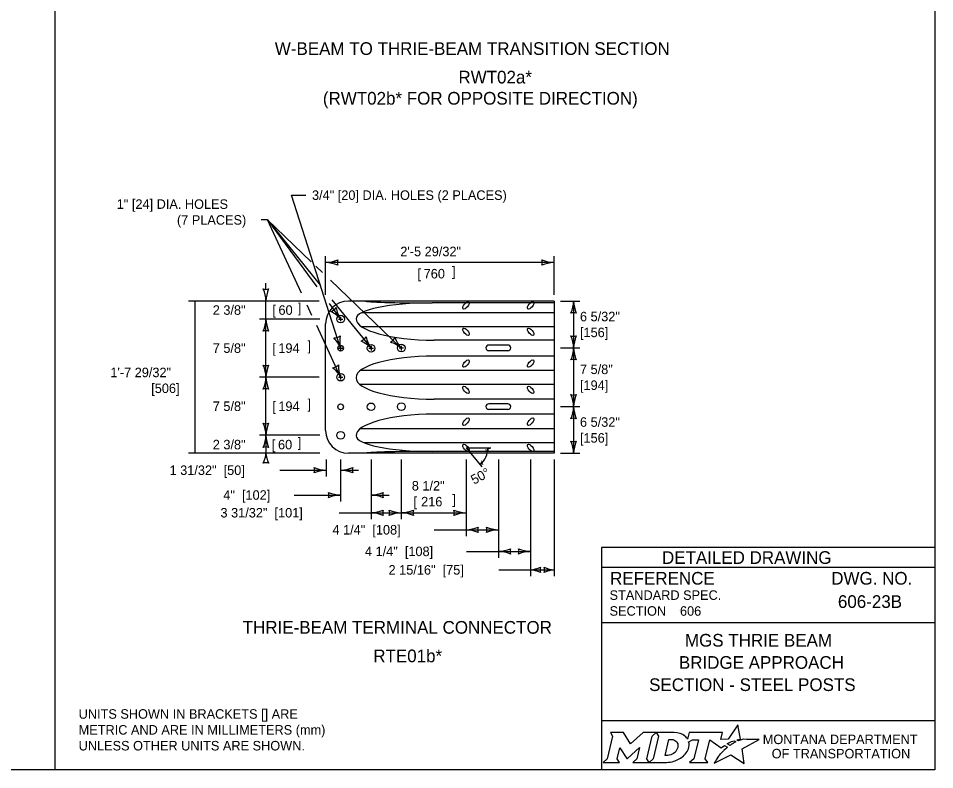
# Model space of a CAD drawing. Extents: x 49991 to 50160, y 49948 to 50051.
# Drawn here: x 50010.97 to 50016.75, y 49987.8 to 49992.54 of the extents above; entities that cross this region are included whole.
import ezdxf

# ---------------------------------------------------------------- set-up
doc = ezdxf.new("R2010")
doc.units = 0
for name, color, linetype in [('Default', 7, 'Continuous'), ('Level 1', 7, 'Continuous'), ('Level 10', 7, 'Continuous'), ('Level 2', 7, 'Continuous'), ('Level 3', 7, 'Continuous'), ('Level 5', 7, 'Continuous')]:
    doc.layers.add(name, color=color, linetype=linetype)

# ---------------------------------------------------------------- blocks, each defined once
blk = doc.blocks.new('ARRP')
at = {"layer": 'Level 10'}
for centre, major_axis, start_param, end_param in [((0.018, 0.564), (0, -0.565), 5.889718, 6.241987), ((-0.253, 0), (0, -0.139), 1.25906, 1.882533), ((0.023, -0.591), (0, 0.592), 0.049346, 0.385319)]:
    blk.add_ellipse(centre, major_axis=major_axis, ratio=0.77736, start_param=start_param, end_param=end_param, dxfattribs=at)

msp = doc.modelspace()

# ---------------------------------------------------------------- linework, layer by layer
at = {"layer": 'Default'}
for points in [[(50015.5126, 49987.9811), (50015.5023, 49987.9867), (50015.5139, 49987.9895), (50015.5255, 49987.9915), (50015.5081, 49988.0816), (50015.4486, 49987.9903), (50015.4013, 49987.9896), (50015.4116, 49988.0337), (50015.2024, 49988.0338), (50015.1923, 49987.9913), (50015.1865, 49987.9996)], [(50014.7056, 49988.0338), (50014.7197, 49988.0104), (50014.6862, 49987.8671), (50014.6605, 49987.8446), (50014.7621, 49987.8446), (50014.7486, 49987.8674), (50014.7648, 49987.9375), (50014.8085, 49987.8685), (50014.8138, 49987.8685), (50014.8889, 49987.938), (50014.8725, 49987.8669), (50014.8478, 49987.8449), (50014.9494, 49987.8449), (50014.9356, 49987.8682), (50014.9688, 49988.0106)], [(50014.9688, 49988.0106), (50014.9941, 49988.0338), (50014.9117, 49988.0338), (50014.8321, 49987.9608), (50014.7876, 49988.0335), (50014.7056, 49988.0338)], [(50015.1077, 49988.0338), (50014.9941, 49988.0338), (50015.0088, 49988.0109), (50014.9749, 49987.8671), (50014.9494, 49987.8449), (50015.06, 49987.8449)], [(50015.1317, 49987.9471), (50015.1305, 49987.939), (50015.1273, 49987.9297), (50015.1231, 49987.9215), (50015.1175, 49987.914), (50015.111, 49987.9071), (50015.1031, 49987.9008), (50015.0948, 49987.8961), (50015.0857, 49987.8922), (50015.0766, 49987.8899), (50015.0674, 49987.889), (50015.0515, 49987.889), (50015.0751, 49987.989), (50015.0911, 49987.989), (50015.0987, 49987.9884), (50015.1063, 49987.9865), (50015.1129, 49987.9835), (50015.119, 49987.9793), (50015.1238, 49987.9743), (50015.1275, 49987.9683), (50015.1302, 49987.9621), (50015.1318, 49987.9547), (50015.1318, 49987.9517), (50015.1317, 49987.9471)], [(50015.1991, 49987.9747), (50015.2237, 49987.9878), (50015.2606, 49987.9878), (50015.232, 49987.8673), (50015.2045, 49987.8446), (50015.3207, 49987.8446), (50015.3037, 49987.8675), (50015.3319, 49987.9877), (50015.4032, 49987.936), (50015.4243, 49987.9511), (50015.444, 49987.9402)], [(50015.3882, 49987.8843), (50015.3729, 49987.8599), (50015.3682, 49987.8524), (50015.3624, 49987.8438), (50015.3601, 49987.8395), (50015.4654, 49987.8926), (50015.5493, 49987.8375), (50015.5362, 49987.9302), (50015.6431, 49987.9886), (50015.5938, 49987.9894), (50015.5637, 49987.9898), (50015.5429, 49987.9901), (50015.5361, 49987.9886), (50015.5312, 49987.9874), (50015.5228, 49987.9851), (50015.5126, 49987.9811)], [(50015.4622, 49987.9535), (50015.4598, 49987.9518), (50015.4415, 49987.9614), (50015.4518, 49987.9671), (50015.4559, 49987.9693), (50015.4645, 49987.9733), (50015.4702, 49987.9759), (50015.4781, 49987.9789), (50015.4854, 49987.9816), (50015.4972, 49987.9742), (50015.4932, 49987.9721), (50015.4886, 49987.9696), (50015.4844, 49987.9674), (50015.4794, 49987.9645), (50015.4775, 49987.9634), (50015.4748, 49987.9618), (50015.4723, 49987.9604), (50015.47, 49987.9588), (50015.4674, 49987.957), (50015.4647, 49987.9552), (50015.4622, 49987.9535)], [(50015.1057, 49987.8522), (50015.1141, 49987.8548), (50015.1271, 49987.8602), (50015.1475, 49987.8712)], [(50015.4021, 49987.9004), (50015.4021, 49987.9004)]]:
    msp.add_lwpolyline(points, dxfattribs=at)
for centre, radius, start, end in [((50015.0868, 49987.9727), 0.1183, 300.91025, 339.13831), ((50015.1308, 49987.9554), 0.0709, 339.53292, 15.85821)]:
    msp.add_arc(centre, radius, start, end, dxfattribs=at)
for centre, major_axis, ratio, start_param, end_param in [((50015.1056, 49987.9864), (0.0834, -0.0037), 0.568097, 0.61298, 1.570796), ((50015.1612, 49987.9937), (0.0361, -0.0295), 0.469099, 1.225588, 1.570796), ((50015.4329, 49987.9305), (-0.0112, -0.0097), 0.021651, 3.157348, 6.283185), ((50015.3952, 49987.8923), (-0.00694, -0.00806), 0.008222, 0, 3.137361), ((50015.4119, 49987.9106), (-0.0098, -0.0102), 0.016458, 3.141593, 6.279097), ((50015.0603, 49987.9932), (0, 0.1484), 0.987302, 3.139398, 3.456847)]:
    msp.add_ellipse(centre, major_axis=major_axis, ratio=ratio, start_param=start_param, end_param=end_param, dxfattribs=at)
at = {"layer": 'Level 1'}
for p, q in [((50014.3502, 49990.7535), (50013.0542, 49990.7535)), ((50014.3502, 49990.7415), (50013.5821, 49990.7415)), ((50014.3502, 49990.7535), (50014.3502, 49989.7935)), ((50014.3502, 49990.6797), (50013.1373, 49990.6797)), ((50012.9102, 49989.9381), (50012.9102, 49990.6095)), ((50014.3502, 49990.5915), (50013.1384, 49990.5915)), ((50014.3502, 49990.5076), (50013.5941, 49990.5076)), ((50014.0593, 49990.4761), (50013.9393, 49990.4761)), ((50014.0593, 49990.4401), (50013.9393, 49990.4401)), ((50014.3502, 49990.4061), (50013.5941, 49990.4061)), ((50014.3502, 49990.3148), (50013.1291, 49990.3148)), ((50014.3502, 49990.2266), (50013.1283, 49990.2266)), ((50014.3502, 49990.1353), (50013.5941, 49990.1353)), ((50014.0593, 49990.1057), (50013.9393, 49990.1057)), ((50014.0593, 49990.0697), (50013.9393, 49990.0697)), ((50014.3502, 49990.0401), (50013.5941, 49990.0401)), ((50014.3502, 49989.9485), (50013.1287, 49989.9485)), ((50014.3502, 49989.8602), (50013.1529, 49989.8602)), ((50014.3502, 49989.7935), (50013.0542, 49989.7935)), ((50014.3502, 49989.8055), (50013.5821, 49989.8055))]:
    msp.add_line(p, q, dxfattribs=at)
msp.add_lwpolyline([(49999.3835, 49998.9992), (50016.7501, 49998.9992), (50016.7501, 49987.7988), (49999.3835, 49987.7988)], close=True, dxfattribs=at)
msp.add_lwpolyline([(50006.474, 49993.358), (50011.2031, 49993.358), (50011.2031, 49987.7988)], dxfattribs=at)
for centre, radius in [((50013.0049, 49990.64), 0.024), ((50013.0049, 49990.4557), 0.018), ((50013.197, 49990.4557), 0.024), ((50013.3875, 49990.4569), 0.024), ((50013.0049, 49990.2735), 0.024), ((50013.0049, 49990.0866), 0.018), ((50013.197, 49990.0866), 0.024), ((50013.3875, 49990.0877), 0.024), ((50013.0049, 49989.9069), 0.024)]:
    msp.add_circle(centre, radius, dxfattribs=at)
for centre, radius, start, end in [((50013.0542, 49990.6095), 0.144, 90, 180), ((50013.9393, 49990.4581), 0.018, 90, 270), ((50014.0593, 49990.4581), 0.018, 270, 90), ((50013.9393, 49990.0877), 0.018, 90, 270), ((50014.0593, 49990.0877), 0.018, 270, 90), ((50013.0542, 49989.9375), 0.144, 180, 270)]:
    msp.add_arc(centre, radius, start, end, dxfattribs=at)
for centre, major_axis, ratio, start_param, end_param in [((50013.5821, 49990.6425), (-0.48, 0), 0.2062, 4.712389, 6.283185), ((50013.5821, 49990.7535), (-0.4208, 0), 0.028516, 0, 1.570796), ((50013.5941, 49990.6425), (-0.492, 0), 0.27561, 0, 1.570796), ((50013.5941, 49990.2705), (-0.492, 0), 0.27561, 4.712389, 6.283185), ((50013.5941, 49990.2702), (-0.492, 0), 0.27561, 0, 1.570796), ((50013.5941, 49989.9045), (-0.492, 0), 0.27561, 4.712389, 6.283185), ((50013.5821, 49989.9045), (-0.48, 0), 0.2062, 0, 1.570796), ((50013.5821, 49989.7935), (-0.4208, 0), 0.028516, 4.712389, 6.283185)]:
    msp.add_ellipse(centre, major_axis=major_axis, ratio=ratio, start_param=start_param, end_param=end_param, dxfattribs=at)
for centre, major_axis in [((50013.7953, 49990.7257), (-0.0182, -0.0217)), ((50014.2029, 49990.7257), (-0.0182, -0.0217)), ((50013.7953, 49990.56), (-0.0182, 0.0217)), ((50014.2029, 49990.56), (-0.0182, 0.0217)), ((50013.7953, 49990.359), (-0.0182, -0.0217)), ((50014.2029, 49990.359), (-0.0182, -0.0217)), ((50013.7953, 49990.1934), (-0.0182, 0.0217)), ((50014.2029, 49990.1934), (-0.0182, 0.0217)), ((50013.7953, 49989.993), (-0.0182, -0.0217)), ((50014.2029, 49989.993), (-0.0182, -0.0217)), ((50013.7953, 49989.8274), (-0.0182, 0.0217)), ((50014.2029, 49989.8274), (-0.0182, 0.0217))]:
    msp.add_ellipse(centre, major_axis=major_axis, ratio=0.447911, dxfattribs=at)
at = {"layer": 'Level 10'}
for centre, major_axis, start_param, end_param in [((50012.3026, 49989.8009), (0.2316, 0), 5.889718, 6.241987), ((50012.7764, 49989.8028), (-0.2427, 0), 0.049346, 0.385319), ((50012.534, 49989.6897), (0.0571, 0), 1.25906, 1.882533), ((50014.1936, 49989.3011), (0, -0.2427), 0.049346, 0.385319), ((50014.1955, 49988.8273), (0, 0.2316), 5.889718, 6.241987), ((50014.3068, 49989.0587), (0, 0.0571), 1.25906, 1.882533), ((50014.3576, 49989.2901), (0, -0.2316), 5.889718, 6.241987), ((50014.2463, 49989.0587), (0, -0.0571), 1.25906, 1.882533), ((50014.3576, 49989.2901), (0, -0.2316), 5.889718, 6.241987), ((50014.2463, 49989.0587), (0, -0.0571), 1.25906, 1.882533), ((50014.3595, 49988.8163), (0, 0.2427), 0.049346, 0.385319), ((50014.3595, 49988.8163), (0, 0.2427), 0.049346, 0.385319)]:
    msp.add_ellipse(centre, major_axis=major_axis, ratio=0.77736, start_param=start_param, end_param=end_param, dxfattribs=at)
at = {"layer": 'Level 3'}
for p, q in [((50013.0049, 49990.4557), (50012.6945, 49991.4213)), ((50012.6945, 49991.4213), (50012.7844, 49991.4213)), ((50012.5439, 49991.2649), (50012.5039, 49991.2649)), ((50012.7588, 49990.8028), (50012.5439, 49991.2649)), ((50012.5439, 49991.2649), (50012.8551, 49990.843)), ((50012.5439, 49991.2649), (50012.8777, 49990.8514)), ((50012.5439, 49991.2649), (50012.8201, 49991.0003)), ((50012.9102, 49990.7935), (50012.9102, 49991.0361)), ((50014.3502, 49990.9961), (50012.9102, 49990.9961)), ((50014.3502, 49990.7935), (50014.3502, 49991.0361)), ((50012.848, 49990.9736), (50012.8907, 49990.9328)), ((50012.9406, 49990.885), (50013.3875, 49990.4569)), ((50012.534, 49990.827), (50012.534, 49990.867)), ((50012.8777, 49990.8514), (50012.8779, 49990.8511)), ((50012.8993, 49990.7831), (50012.8998, 49990.7824)), ((50012.9503, 49990.7615), (50013.197, 49990.4557)), ((50012.8702, 49990.7535), (50012.0464, 49990.7535)), ((50012.0864, 49990.7535), (50012.0864, 49989.7935)), ((50012.534, 49990.64), (50012.534, 49990.7535)), ((50012.8238, 49990.6629), (50012.7936, 49990.7278)), ((50012.9329, 49990.7376), (50013.0049, 49990.64)), ((50014.3902, 49990.7535), (50014.5138, 49990.7535)), ((50014.4738, 49990.7535), (50014.4738, 49990.4581)), ((50013.0049, 49990.6544), (50013.0049, 49990.6256)), ((50012.8735, 49990.64), (50012.494, 49990.64)), ((50012.534, 49990.2735), (50012.534, 49990.64)), ((50013.0049, 49990.2735), (50012.8538, 49990.5983)), ((50012.9905, 49990.64), (50013.0193, 49990.64)), ((50013.0049, 49990.4701), (50013.0049, 49990.4413)), ((50013.197, 49990.4701), (50013.197, 49990.4413)), ((50013.3875, 49990.4713), (50013.3875, 49990.4425)), ((50012.9905, 49990.4569), (50013.0193, 49990.4569)), ((50013.1826, 49990.4569), (50013.2114, 49990.4569)), ((50013.3731, 49990.458), (50013.4019, 49990.458)), ((50014.3902, 49990.4581), (50014.5138, 49990.4581)), ((50014.4738, 49990.4581), (50014.4738, 49990.0877)), ((50012.8702, 49990.2735), (50012.494, 49990.2735)), ((50012.534, 49989.9069), (50012.534, 49990.2735)), ((50012.9905, 49990.2735), (50013.0193, 49990.2735)), ((50013.0049, 49990.2879), (50013.0049, 49990.2591)), ((50014.3902, 49990.0877), (50014.5138, 49990.0877)), ((50014.4738, 49990.0877), (50014.4738, 49989.7935)), ((50012.8735, 49989.9069), (50012.494, 49989.9069)), ((50012.534, 49989.9069), (50012.534, 49989.7935)), ((50012.8735, 49989.7935), (50012.0464, 49989.7935)), ((50013.7953, 49989.8274), (50013.8961, 49989.7072)), ((50013.7953, 49989.8274), (50013.9521, 49989.8274)), ((50014.3902, 49989.7935), (50014.5138, 49989.7935)), ((50012.9135, 49989.7535), (50012.9135, 49989.6469)), ((50013.0049, 49989.7535), (50013.0049, 49989.4905)), ((50013.197, 49989.7535), (50013.197, 49989.3788)), ((50013.3875, 49989.7535), (50013.3875, 49989.3788)), ((50013.7953, 49989.7535), (50013.7953, 49989.2714)), ((50013.9993, 49989.7535), (50014, 49989.1352)), ((50014.2029, 49989.754), (50014.2029, 49989.0187)), ((50014.3502, 49989.7535), (50014.3502, 49989.0187)), ((50012.6207, 49989.6869), (50012.9135, 49989.6869)), ((50012.7121, 49989.5305), (50013.0049, 49989.5305)), ((50012.9954, 49989.4188), (50013.3875, 49989.4188)), ((50013.3875, 49989.4188), (50013.7953, 49989.4188)), ((50013.5937, 49989.3114), (50013.9993, 49989.3114)), ((50013.7987, 49989.1752), (50014.204, 49989.1752)), ((50014.0013, 49989.0587), (50014.3502, 49989.0587))]:
    msp.add_line(p, q, dxfattribs=at)
for points in [[(50013.0049, 49989.6869), (50013.0783, 49989.6869), (50013.1183, 49989.6869)], [(50013.197, 49989.5305), (50013.2705, 49989.5305), (50013.3105, 49989.5305)]]:
    msp.add_lwpolyline(points, dxfattribs=at)
for centre, radius, start, end in [((50012.8987, 49991.2288), 0.233, 272.82731, 292.07716), ((50012.901, 49990.774), 0.2223, 67.45601, 87.63952), ((50013.0384, 49990.9961), 0.0548, 162.13882, 197.86118), ((50014.3593, 49991.2183), 0.2223, 247.45601, 267.63952), ((50014.222, 49990.9961), 0.0548, 342.13882, 17.86118), ((50014.3617, 49990.7634), 0.233, 92.82731, 112.07716), ((50012.534, 49990.8817), 0.0548, 252.13882, 287.86118), ((50012.3013, 49990.742), 0.233, 2.82731, 22.07716), ((50012.7561, 49990.7444), 0.2223, 157.45601, 177.63952), ((50014.2516, 49990.7627), 0.2223, 337.45601, 357.63952), ((50014.7065, 49990.765), 0.233, 182.82731, 202.07716), ((50014.4738, 49990.6253), 0.0548, 72.13882, 107.86118), ((50012.3118, 49990.6492), 0.2223, 337.45601, 357.63952), ((50012.7667, 49990.6515), 0.233, 182.82731, 202.07716), ((50012.534, 49990.5118), 0.0548, 72.13882, 107.86118), ((50014.4738, 49990.5863), 0.0548, 252.13882, 287.86118), ((50014.2411, 49990.4466), 0.233, 2.82731, 22.07716), ((50014.6959, 49990.449), 0.2223, 157.45601, 177.63952), ((50014.2516, 49990.4673), 0.2223, 337.45601, 357.63952), ((50014.7065, 49990.4696), 0.233, 182.82731, 202.07716), ((50014.4738, 49990.3299), 0.0548, 72.13882, 107.86118), ((50012.534, 49990.4017), 0.0548, 252.13882, 287.86118), ((50012.3013, 49990.262), 0.233, 2.82731, 22.07716), ((50012.7561, 49990.2643), 0.2223, 157.45601, 177.63952), ((50012.3118, 49990.2826), 0.2223, 337.45601, 357.63952), ((50012.7667, 49990.285), 0.233, 182.82731, 202.07716), ((50012.534, 49990.1452), 0.0548, 72.13882, 107.86118), ((50014.4738, 49990.2159), 0.0548, 252.13882, 287.86118), ((50014.2411, 49990.0762), 0.233, 2.82731, 22.07716), ((50014.6959, 49990.0786), 0.2223, 157.45601, 177.63952), ((50014.2516, 49990.0969), 0.2223, 337.45601, 357.63952), ((50014.7065, 49990.0992), 0.233, 182.82731, 202.07716), ((50014.4738, 49989.9595), 0.0548, 72.13882, 107.86118), ((50012.534, 49990.0351), 0.0548, 252.13882, 287.86118), ((50012.3013, 49989.8954), 0.233, 2.82731, 22.07716), ((50012.7561, 49989.8977), 0.2223, 157.45601, 177.63952), ((50012.3118, 49989.9161), 0.2223, 337.45601, 357.63952), ((50012.7667, 49989.9184), 0.233, 182.82731, 202.07716), ((50012.534, 49989.7787), 0.0548, 72.13882, 107.86118), ((50014.4738, 49989.9217), 0.0548, 252.13882, 287.86118), ((50014.2411, 49989.782), 0.233, 2.82731, 22.07716), ((50014.6959, 49989.7844), 0.2223, 157.45601, 177.63952), ((50013.7953, 49989.8274), 0.1376, 310, 360), ((50012.9226, 49989.9091), 0.2223, 247.45601, 267.63952), ((50012.7853, 49989.6869), 0.0548, 342.13882, 17.86118), ((50012.925, 49989.4542), 0.233, 92.82731, 112.07716), ((50012.9934, 49989.9197), 0.233, 272.82731, 292.07716), ((50012.9957, 49989.4648), 0.2223, 67.45601, 87.63952), ((50013.1331, 49989.6869), 0.0548, 162.13882, 197.86118), ((50013.014, 49989.7526), 0.2223, 247.45601, 267.63952), ((50012.8766, 49989.5305), 0.0548, 342.13882, 17.86118), ((50013.1855, 49989.7632), 0.233, 272.82731, 292.07716), ((50013.3252, 49989.5305), 0.0548, 162.13882, 197.86118), ((50013.0164, 49989.2977), 0.233, 92.82731, 112.07716), ((50013.1879, 49989.3083), 0.2223, 67.45601, 87.63952), ((50013.1855, 49989.6515), 0.233, 272.82731, 292.07716), ((50013.3252, 49989.4188), 0.0548, 162.13882, 197.86118), ((50013.3967, 49989.641), 0.2223, 247.45601, 267.63952), ((50013.2593, 49989.4188), 0.0548, 342.13882, 17.86118), ((50013.376, 49989.6515), 0.233, 272.82731, 292.07716), ((50013.5157, 49989.4188), 0.0548, 162.13882, 197.86118), ((50013.8045, 49989.641), 0.2223, 247.45601, 267.63952), ((50013.6671, 49989.4188), 0.0548, 342.13882, 17.86118), ((50013.1879, 49989.1967), 0.2223, 67.45601, 87.63952), ((50013.399, 49989.1861), 0.233, 92.82731, 112.07716), ((50013.3784, 49989.1967), 0.2223, 67.45601, 87.63952), ((50013.8068, 49989.1861), 0.233, 92.82731, 112.07716), ((50013.7838, 49989.5441), 0.233, 272.82731, 292.07716), ((50013.9235, 49989.3114), 0.0548, 162.13882, 197.86118), ((50014.0089, 49989.5336), 0.2223, 247.45601, 267.63952), ((50013.8716, 49989.3114), 0.0548, 342.13882, 17.86118), ((50013.7862, 49989.0893), 0.2223, 67.45601, 87.63952), ((50014.0113, 49989.0787), 0.233, 92.82731, 112.07716), ((50013.9884, 49989.408), 0.233, 272.82731, 292.07716), ((50013.9908, 49988.9531), 0.2223, 67.45601, 87.63952), ((50014.1281, 49989.1752), 0.0548, 162.13882, 197.86118), ((50014.2121, 49989.3974), 0.2223, 247.45601, 267.63952), ((50014.0747, 49989.1752), 0.0548, 342.13882, 17.86118), ((50014.2144, 49988.9425), 0.233, 92.82731, 112.07716)]:
    msp.add_arc(centre, radius, start, end, dxfattribs=at)
at = {"layer": 'Level 5'}
for p, q in [((50016.7501, 49989.1988), (50014.6501, 49989.1988)), ((50014.6501, 49989.1988), (50014.6501, 49987.7988)), ((50016.7501, 49989.0738), (50014.6501, 49989.0738)), ((50016.3862, 49988.8587), (50016.3862, 49988.8587)), ((50015.1444, 49988.7993), (50015.1444, 49988.7993)), ((50016.7501, 49988.7238), (50014.6501, 49988.7238)), ((50015.7001, 49988.4747), (50015.7001, 49988.4747)), ((50016.7501, 49988.1057), (50014.6501, 49988.1057))]:
    msp.add_line(p, q, dxfattribs=at)

# ---------------------------------------------------------------- block references
at = {"layer": 'Level 3'}
for p, xscale, yscale, rotation in [((50013.0049, 49990.64), 0.5000000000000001, 0.5, -53.585703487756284), ((50013.0049, 49990.4557), 0.5000000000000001, 0.5, -72.17893826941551), ((50013.0049, 49990.4557), 0.5000000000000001, 0.5, -72.17893826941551), ((50013.197, 49990.4557), 0.5000000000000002, 0.4999999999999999, -51.093024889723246), ((50013.197, 49990.4557), 0.5000000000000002, 0.4999999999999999, -51.093024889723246), ((50013.3875, 49990.4569), 0.5, 0.5, -43.76640499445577), ((50013.3875, 49990.4569), 0.5, 0.5, -43.76640499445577), ((50013.0049, 49990.2735), 0.5000000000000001, 0.5, -65.06566668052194), ((50013.0049, 49990.2735), 0.5000000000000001, 0.5, -65.06566668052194)]:
    msp.add_blockref('ARRP', p, dxfattribs=dict(at, xscale=xscale, yscale=yscale, rotation=rotation))

# ---------------------------------------------------------------- texts
at = {"layer": 'Default'}
for s, p in [('MONTANA DEPARTMENT', (50015.6663, 49987.96)), ('OF TRANSPORTATION', (50015.7225, 49987.87))]:
    msp.add_text(s, height=0.06, dxfattribs=at).set_placement(p)
at = {"layer": 'Level 2'}
for s, height, p in [('W-BEAM TO THRIE-BEAM TRANSITION SECTION', 0.08, (50012.5898, 49992.3053)), ('RWT02a*', 0.08, (50013.7476, 49992.1253)), ('(RWT02b* FOR OPPOSITE DIRECTION)', 0.08, (50012.8929, 49991.9919)), ('2\'-5 29/32"', 0.06, (50013.3811, 49991.0361)), ('[', 0.06, (50013.4895, 49990.8961)), ('760', 0.06, (50013.5285, 49990.8961)), ('2 3/8"', 0.06, (50012.1986, 49990.6668)), ('[', 0.06, (50012.574, 49990.6668)), ('60', 0.06, (50012.613, 49990.6667)), ('6 5/32"', 0.06, (50014.5138, 49990.6258)), ('[156]', 0.06, (50014.5138, 49990.5258)), ('7 5/8"', 0.06, (50012.1986, 49990.4267)), ('[', 0.06, (50012.574, 49990.4267)), ('194', 0.06, (50012.6121, 49990.4267)), ('7 5/8"', 0.06, (50014.5138, 49990.2929)), ('1\'-7 29/32"', 0.06, (50011.553, 49990.2735)), ('[194]', 0.06, (50014.5138, 49990.1929)), ('[506]', 0.06, (50011.8107, 49990.1735)), ('7 5/8"', 0.06, (50012.1986, 49990.0602)), ('[', 0.06, (50012.574, 49990.0602)), ('194', 0.06, (50012.6121, 49990.0602)), ('6 5/32"', 0.06, (50014.5138, 49989.9606)), ('[156]', 0.06, (50014.5138, 49989.8606)), ('2 3/8"', 0.06, (50012.1986, 49989.8184)), ('[', 0.06, (50012.5711, 49989.8184)), ('60', 0.06, (50012.6101, 49989.8184)), ('1 31/32"  [50]', 0.06, (50011.9263, 49989.6569)), ('8 1/2"', 0.06, (50013.4536, 49989.5588)), ('4"  [102]', 0.06, (50012.2651, 49989.5005)), ('[', 0.06, (50013.4643, 49989.4588)), ('216', 0.06, (50013.5123, 49989.4588)), ('3 31/32"  [101]', 0.06, (50012.2472, 49989.3888)), ('4 1/4"  [108]', 0.06, (50012.9533, 49989.2814)), ('4 1/4"  [108]', 0.06, (50013.1582, 49989.1452)), ('2 15/16"  [75]', 0.06, (50013.307, 49989.0287)), ('606-23B', 0.08, (50016.1401, 49988.8187)), ('606', 0.06, (50015.1444, 49988.7693)), ('THRIE-BEAM TERMINAL CONNECTOR', 0.08, (50012.3874, 49988.6561)), ('MGS THRIE BEAM', 0.08, (50015.1757, 49988.5747)), ('RTE01b*', 0.08, (50013.2106, 49988.4761)), ('BRIDGE APPROACH', 0.08, (50015.1375, 49988.4347)), ('SECTION - STEEL POSTS', 0.08, (50014.9497, 49988.2947)), ('UNITS SHOWN IN BRACKETS [] ARE ', 0.06, (50011.3531, 49988.12)), ('METRIC AND ARE IN MILLIMETERS (mm) ', 0.06, (50011.3531, 49988.02)), ('UNLESS OTHER UNITS ARE SHOWN.', 0.06, (50011.3531, 49987.92))]:
    msp.add_text(s, height=height, dxfattribs=at).set_placement(p)
for s, rotation, p in [('3/4" [20] DIA. HOLES (2 PLACES)', 360, (50012.8244, 49991.3913)), ('1" [24] DIA. HOLES', 360, (50011.5933, 49991.3348)), ('(7 PLACES)', 360, (50011.9728, 49991.2349)), ('[', 180, (50013.7292, 49990.9562)), ('[', 180, (50012.757, 49990.726)), ('[', 180, (50012.8179, 49990.4867)), ('[', 180, (50012.8179, 49990.1202)), ('[', 180, (50012.7574, 49989.8784)), ('50°', 28.00927, (50013.8458, 49989.5951)), ('[', 180, (50013.7317, 49989.5188))]:
    msp.add_text(s, height=0.06, rotation=rotation, dxfattribs=at).set_placement(p)
at = {"layer": 'Level 3'}
for rotation, p in [(83.99364, (50013.9445, 49989.7992)), (226.00636, (50013.892, 49989.7512))]:
    msp.add_text('A', height=0.0288, rotation=rotation, dxfattribs=at).set_placement(p)
at = {"layer": 'Level 5'}
for s, height, p in [('DETAILED DRAWING', 0.0799, (50015.0311, 49989.0963)), ('REFERENCE', 0.08, (50014.7037, 49988.9654)), ('DWG. NO.', 0.08, (50016.0979, 49988.9654)), ('STANDARD SPEC.', 0.06, (50014.7004, 49988.8694)), ('SECTION', 0.06, (50014.7004, 49988.7694))]:
    msp.add_text(s, height=height, dxfattribs=at).set_placement(p)

doc.saveas('drawing.dxf')
